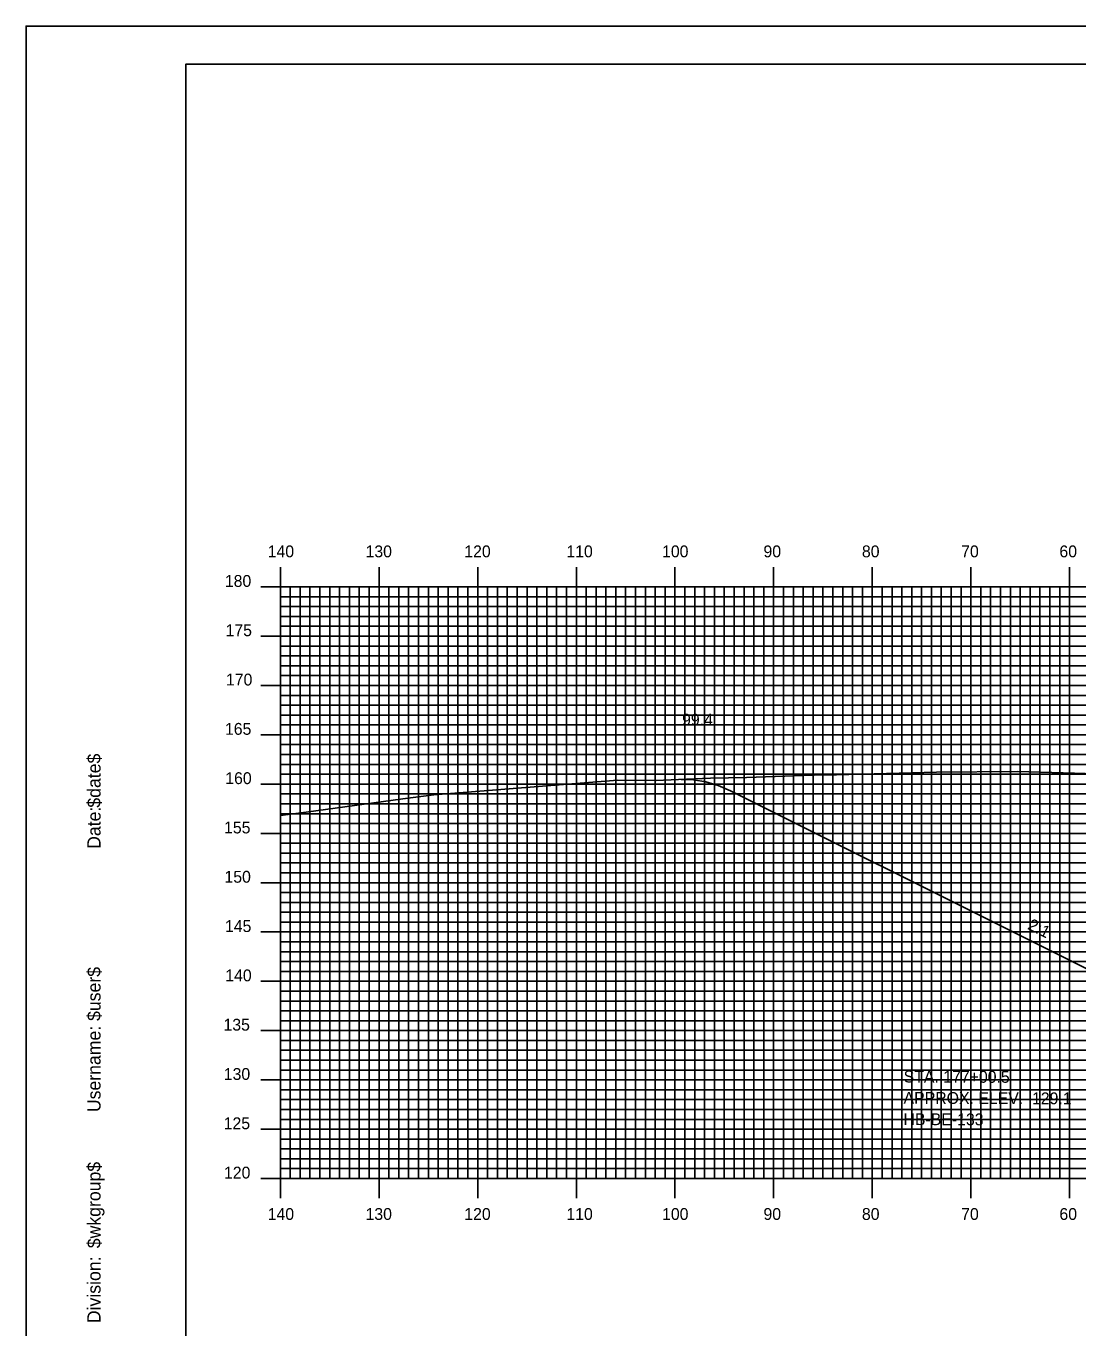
# Model space of a CAD drawing. Extents: x 1784615 to 1784958, y 442591 to 442811.
# Drawn here: x 1784614.7 to 1784721.4, y 442678.5 to 442810.5 of the extents above; entities that cross this region are included whole.
import ezdxf

# ---------------------------------------------------------------- set-up
doc = ezdxf.new("R2010")
doc.units = 0
for name, color, linetype in [('ANNOTATION', 7, 'Continuous'), ('BORDER', 7, 'Continuous'), ('BORING - NO REFUSAL', 7, 'Continuous'), ('D_Roadway_SlopeLines', 7, 'Continuous'), ('D_Text_Standard', 7, 'Continuous'), ('H_V ANNOTATION', 7, 'Continuous'), ('MAJOR', 7, 'Continuous'), ('MINOR', 7, 'Continuous'), ('PLOT BOUNDARY', 7, 'Continuous'), ('S_Roadway_Centerline', 7, 'Continuous')]:
    doc.layers.add(name, color=color, linetype=linetype)

msp = doc.modelspace()

# ---------------------------------------------------------------- linework, layer by layer
at = {"layer": 'BORDER'}
msp.add_lwpolyline([(1784630.91, 442596.67), (1784950.91, 442596.67), (1784950.91, 442806.67), (1784630.91, 442806.67)], close=True, dxfattribs=at)
at = {"layer": 'D_Roadway_SlopeLines'}
msp.add_lwpolyline([(1784746.34, 442702.89), (1784686.14, 442732.99), (1784684.89, 442733.53), (1784683.64, 442733.91), (1784682.39, 442734.11), (1784681.14, 442734.14)], dxfattribs=at)
at = {"layer": 'MAJOR'}
for p, q in [((1784640.51, 442755.67), (1784640.51, 442753.67)), ((1784650.51, 442755.67), (1784650.51, 442753.67)), ((1784660.51, 442755.67), (1784660.51, 442753.67)), ((1784670.51, 442755.67), (1784670.51, 442753.67)), ((1784680.51, 442755.67), (1784680.51, 442753.67)), ((1784690.51, 442755.67), (1784690.51, 442753.67)), ((1784700.51, 442755.67), (1784700.51, 442753.67)), ((1784710.51, 442755.67), (1784710.51, 442753.67)), ((1784720.51, 442755.67), (1784720.51, 442753.67)), ((1784638.51, 442753.67), (1784640.51, 442753.67)), ((1784640.51, 442753.67), (1784920.51, 442753.67)), ((1784640.51, 442693.67), (1784640.51, 442753.67)), ((1784640.51, 442693.67), (1784640.51, 442753.67)), ((1784640.51, 442753.67), (1784920.51, 442753.67)), ((1784650.51, 442693.67), (1784650.51, 442753.67)), ((1784660.51, 442693.67), (1784660.51, 442753.67)), ((1784670.51, 442693.67), (1784670.51, 442753.67)), ((1784680.51, 442693.67), (1784680.51, 442753.67)), ((1784690.51, 442693.67), (1784690.51, 442753.67)), ((1784700.51, 442693.67), (1784700.51, 442753.67)), ((1784710.51, 442693.67), (1784710.51, 442753.67)), ((1784720.51, 442693.67), (1784720.51, 442753.67)), ((1784638.51, 442748.67), (1784640.51, 442748.67)), ((1784640.51, 442748.67), (1784920.51, 442748.67)), ((1784638.51, 442743.67), (1784640.51, 442743.67)), ((1784640.51, 442743.67), (1784920.51, 442743.67)), ((1784638.51, 442738.67), (1784640.51, 442738.67)), ((1784640.51, 442738.67), (1784920.51, 442738.67)), ((1784638.51, 442733.67), (1784640.51, 442733.67)), ((1784640.51, 442733.67), (1784920.51, 442733.67)), ((1784638.51, 442728.67), (1784640.51, 442728.67)), ((1784640.51, 442728.67), (1784920.51, 442728.67)), ((1784638.51, 442723.67), (1784640.51, 442723.67)), ((1784640.51, 442723.67), (1784920.51, 442723.67)), ((1784638.51, 442718.67), (1784640.51, 442718.67)), ((1784640.51, 442718.67), (1784920.51, 442718.67)), ((1784638.51, 442713.67), (1784640.51, 442713.67)), ((1784640.51, 442713.67), (1784920.51, 442713.67)), ((1784638.51, 442708.67), (1784640.51, 442708.67)), ((1784640.51, 442708.67), (1784920.51, 442708.67)), ((1784638.51, 442703.67), (1784640.51, 442703.67)), ((1784640.51, 442703.67), (1784920.51, 442703.67)), ((1784638.51, 442698.67), (1784640.51, 442698.67)), ((1784640.51, 442698.67), (1784920.51, 442698.67)), ((1784638.51, 442693.67), (1784640.51, 442693.67)), ((1784640.51, 442693.67), (1784920.51, 442693.67)), ((1784640.51, 442693.67), (1784920.51, 442693.67)), ((1784640.51, 442691.66), (1784640.51, 442693.67)), ((1784650.51, 442691.66), (1784650.51, 442693.67)), ((1784660.51, 442691.66), (1784660.51, 442693.67)), ((1784670.51, 442691.66), (1784670.51, 442693.67)), ((1784680.51, 442691.66), (1784680.51, 442693.67)), ((1784690.51, 442691.66), (1784690.51, 442693.67)), ((1784700.51, 442691.66), (1784700.51, 442693.67)), ((1784710.51, 442691.66), (1784710.51, 442693.67)), ((1784720.51, 442691.66), (1784720.51, 442693.67))]:
    msp.add_line(p, q, dxfattribs=at)
at = {"layer": 'MINOR'}
for p, q in [((1784641.51, 442693.67), (1784641.51, 442753.67)), ((1784642.51, 442693.67), (1784642.51, 442753.67)), ((1784643.51, 442693.67), (1784643.51, 442753.67)), ((1784644.51, 442693.67), (1784644.51, 442753.67)), ((1784645.51, 442693.67), (1784645.51, 442753.67)), ((1784646.51, 442693.67), (1784646.51, 442753.67)), ((1784647.51, 442693.67), (1784647.51, 442753.67)), ((1784648.51, 442693.67), (1784648.51, 442753.67)), ((1784649.51, 442693.67), (1784649.51, 442753.67)), ((1784651.51, 442693.67), (1784651.51, 442753.67)), ((1784652.51, 442693.67), (1784652.51, 442753.67)), ((1784653.51, 442693.67), (1784653.51, 442753.67)), ((1784654.51, 442693.67), (1784654.51, 442753.67)), ((1784655.51, 442693.67), (1784655.51, 442753.67)), ((1784656.51, 442693.67), (1784656.51, 442753.67)), ((1784657.51, 442693.67), (1784657.51, 442753.67)), ((1784658.51, 442693.67), (1784658.51, 442753.67)), ((1784659.51, 442693.67), (1784659.51, 442753.67)), ((1784661.51, 442693.67), (1784661.51, 442753.67)), ((1784662.51, 442693.67), (1784662.51, 442753.67)), ((1784663.51, 442693.67), (1784663.51, 442753.67)), ((1784664.51, 442693.67), (1784664.51, 442753.67)), ((1784665.51, 442693.67), (1784665.51, 442753.67)), ((1784666.51, 442693.67), (1784666.51, 442753.67)), ((1784667.51, 442693.67), (1784667.51, 442753.67)), ((1784668.51, 442693.67), (1784668.51, 442753.67)), ((1784669.51, 442693.67), (1784669.51, 442753.67)), ((1784671.51, 442693.67), (1784671.51, 442753.67)), ((1784672.51, 442693.67), (1784672.51, 442753.67)), ((1784673.51, 442693.67), (1784673.51, 442753.67)), ((1784674.51, 442693.67), (1784674.51, 442753.67)), ((1784675.51, 442693.67), (1784675.51, 442753.67)), ((1784676.51, 442693.67), (1784676.51, 442753.67)), ((1784677.51, 442693.67), (1784677.51, 442753.67)), ((1784678.51, 442693.67), (1784678.51, 442753.67)), ((1784679.51, 442693.67), (1784679.51, 442753.67)), ((1784681.51, 442693.67), (1784681.51, 442753.67)), ((1784682.51, 442693.67), (1784682.51, 442753.67)), ((1784683.51, 442693.67), (1784683.51, 442753.67)), ((1784684.51, 442693.67), (1784684.51, 442753.67)), ((1784685.51, 442693.67), (1784685.51, 442753.67)), ((1784686.51, 442693.67), (1784686.51, 442753.67)), ((1784687.51, 442693.67), (1784687.51, 442753.67)), ((1784688.51, 442693.67), (1784688.51, 442753.67)), ((1784689.51, 442693.67), (1784689.51, 442753.67)), ((1784691.51, 442693.67), (1784691.51, 442753.67)), ((1784692.51, 442693.67), (1784692.51, 442753.67)), ((1784693.51, 442693.67), (1784693.51, 442753.67)), ((1784694.51, 442693.67), (1784694.51, 442753.67)), ((1784695.51, 442693.67), (1784695.51, 442753.67)), ((1784696.51, 442693.67), (1784696.51, 442753.67)), ((1784697.51, 442693.67), (1784697.51, 442753.67)), ((1784698.51, 442693.67), (1784698.51, 442753.67)), ((1784699.51, 442693.67), (1784699.51, 442753.67)), ((1784701.51, 442693.67), (1784701.51, 442753.67)), ((1784702.51, 442693.67), (1784702.51, 442753.67)), ((1784703.51, 442693.67), (1784703.51, 442753.67)), ((1784704.51, 442693.67), (1784704.51, 442753.67)), ((1784705.51, 442693.67), (1784705.51, 442753.67)), ((1784706.51, 442693.67), (1784706.51, 442753.67)), ((1784707.51, 442693.67), (1784707.51, 442753.67)), ((1784708.51, 442693.67), (1784708.51, 442753.67)), ((1784709.51, 442693.67), (1784709.51, 442753.67)), ((1784711.51, 442693.67), (1784711.51, 442753.67)), ((1784712.51, 442693.67), (1784712.51, 442753.67)), ((1784713.51, 442693.67), (1784713.51, 442753.67)), ((1784714.51, 442693.67), (1784714.51, 442753.67)), ((1784715.51, 442693.67), (1784715.51, 442753.67)), ((1784716.51, 442693.67), (1784716.51, 442753.67)), ((1784717.51, 442693.67), (1784717.51, 442753.67)), ((1784718.51, 442693.67), (1784718.51, 442753.67)), ((1784719.51, 442693.67), (1784719.51, 442753.67)), ((1784640.51, 442752.67), (1784920.51, 442752.67)), ((1784640.51, 442752.67), (1784642.52, 442752.67)), ((1784640.51, 442751.67), (1784920.51, 442751.67)), ((1784640.51, 442751.67), (1784642.52, 442751.67)), ((1784640.51, 442750.67), (1784920.51, 442750.67)), ((1784640.51, 442750.67), (1784642.52, 442750.67)), ((1784640.51, 442749.67), (1784920.51, 442749.67)), ((1784640.51, 442749.67), (1784642.52, 442749.67)), ((1784640.51, 442747.67), (1784920.51, 442747.67)), ((1784640.51, 442747.67), (1784642.52, 442747.67)), ((1784640.51, 442746.67), (1784920.51, 442746.67)), ((1784640.51, 442746.67), (1784642.52, 442746.67)), ((1784640.51, 442745.67), (1784920.51, 442745.67)), ((1784640.51, 442745.67), (1784642.52, 442745.67)), ((1784640.51, 442744.67), (1784920.51, 442744.67)), ((1784640.51, 442744.67), (1784642.52, 442744.67)), ((1784640.51, 442742.67), (1784920.51, 442742.67)), ((1784640.51, 442742.67), (1784642.52, 442742.67)), ((1784640.51, 442741.67), (1784920.51, 442741.67)), ((1784640.51, 442741.67), (1784642.52, 442741.67)), ((1784640.51, 442740.67), (1784920.51, 442740.67)), ((1784640.51, 442740.67), (1784642.52, 442740.67)), ((1784640.51, 442739.67), (1784920.51, 442739.67)), ((1784640.51, 442739.67), (1784642.52, 442739.67)), ((1784640.51, 442737.67), (1784920.51, 442737.67)), ((1784640.51, 442737.67), (1784642.52, 442737.67)), ((1784640.51, 442736.67), (1784920.51, 442736.67)), ((1784640.51, 442736.67), (1784642.52, 442736.67)), ((1784640.51, 442735.67), (1784920.51, 442735.67)), ((1784640.51, 442735.67), (1784642.52, 442735.67)), ((1784640.51, 442734.67), (1784920.51, 442734.67)), ((1784640.51, 442734.67), (1784642.52, 442734.67)), ((1784640.51, 442732.67), (1784920.51, 442732.67)), ((1784640.51, 442732.67), (1784642.52, 442732.67)), ((1784640.51, 442731.67), (1784920.51, 442731.67)), ((1784640.51, 442731.67), (1784642.52, 442731.67)), ((1784640.51, 442730.67), (1784920.51, 442730.67)), ((1784640.51, 442730.67), (1784642.52, 442730.67)), ((1784640.51, 442729.67), (1784920.51, 442729.67)), ((1784640.51, 442729.67), (1784642.52, 442729.67)), ((1784640.51, 442727.67), (1784920.51, 442727.67)), ((1784640.51, 442727.67), (1784642.52, 442727.67)), ((1784640.51, 442726.67), (1784920.51, 442726.67)), ((1784640.51, 442726.67), (1784642.52, 442726.67)), ((1784640.51, 442725.67), (1784920.51, 442725.67)), ((1784640.51, 442725.67), (1784642.52, 442725.67)), ((1784640.51, 442724.67), (1784920.51, 442724.67)), ((1784640.51, 442724.67), (1784642.52, 442724.67)), ((1784640.51, 442722.67), (1784920.51, 442722.67)), ((1784640.51, 442722.67), (1784642.52, 442722.67)), ((1784640.51, 442721.67), (1784920.51, 442721.67)), ((1784640.51, 442721.67), (1784642.52, 442721.67)), ((1784640.51, 442720.67), (1784920.51, 442720.67)), ((1784640.51, 442720.67), (1784642.52, 442720.67)), ((1784640.51, 442719.67), (1784920.51, 442719.67)), ((1784640.51, 442719.67), (1784642.52, 442719.67)), ((1784640.51, 442717.67), (1784920.51, 442717.67)), ((1784640.51, 442717.67), (1784642.52, 442717.67)), ((1784640.51, 442716.67), (1784920.51, 442716.67)), ((1784640.51, 442716.67), (1784642.52, 442716.67)), ((1784640.51, 442715.67), (1784920.51, 442715.67)), ((1784640.51, 442715.67), (1784642.52, 442715.67)), ((1784640.51, 442714.67), (1784920.51, 442714.67)), ((1784640.51, 442714.67), (1784642.52, 442714.67)), ((1784640.51, 442712.67), (1784920.51, 442712.67)), ((1784640.51, 442712.67), (1784642.52, 442712.67)), ((1784640.51, 442711.67), (1784920.51, 442711.67)), ((1784640.51, 442711.67), (1784642.52, 442711.67)), ((1784640.51, 442710.67), (1784920.51, 442710.67)), ((1784640.51, 442710.67), (1784642.52, 442710.67)), ((1784640.51, 442709.67), (1784920.51, 442709.67)), ((1784640.51, 442709.67), (1784642.52, 442709.67)), ((1784640.51, 442707.67), (1784920.51, 442707.67)), ((1784640.51, 442707.67), (1784642.52, 442707.67)), ((1784640.51, 442706.67), (1784920.51, 442706.67)), ((1784640.51, 442706.67), (1784642.52, 442706.67)), ((1784640.51, 442705.67), (1784920.51, 442705.67)), ((1784640.51, 442705.67), (1784642.52, 442705.67)), ((1784640.51, 442704.67), (1784920.51, 442704.67)), ((1784640.51, 442704.67), (1784642.52, 442704.67)), ((1784640.51, 442702.67), (1784920.51, 442702.67)), ((1784640.51, 442702.67), (1784642.52, 442702.67)), ((1784640.51, 442701.67), (1784920.51, 442701.67)), ((1784640.51, 442701.67), (1784642.52, 442701.67)), ((1784640.51, 442700.67), (1784920.51, 442700.67)), ((1784640.51, 442700.67), (1784642.52, 442700.67)), ((1784640.51, 442699.67), (1784920.51, 442699.67)), ((1784640.51, 442699.67), (1784642.52, 442699.67)), ((1784640.51, 442697.67), (1784920.51, 442697.67)), ((1784640.51, 442697.67), (1784642.52, 442697.67)), ((1784640.51, 442696.67), (1784920.51, 442696.67)), ((1784640.51, 442696.67), (1784642.52, 442696.67)), ((1784640.51, 442695.67), (1784920.51, 442695.67)), ((1784640.51, 442695.67), (1784642.52, 442695.67)), ((1784640.51, 442694.67), (1784920.51, 442694.67)), ((1784640.51, 442694.67), (1784642.52, 442694.67))]:
    msp.add_line(p, q, dxfattribs=at)
at = {"layer": 'PLOT BOUNDARY'}
msp.add_lwpolyline([(1784614.73, 442590.55), (1784954.73, 442590.55), (1784954.73, 442810.55), (1784614.73, 442810.55)], close=True, dxfattribs=at)
at = {"layer": 'S_Roadway_Centerline'}
msp.add_lwpolyline([(1784640.51, 442730.48), (1784643.12, 442730.83), (1784652.92, 442732.17), (1784656.05, 442732.57), (1784674.71, 442734.07), (1784678.59, 442734.04), (1784680.88, 442734.13), (1784684.11, 442734.26), (1784687.77, 442734.35), (1784693.57, 442734.55), (1784695.65, 442734.62), (1784696.89, 442734.61), (1784707.03, 442734.89), (1784715.23, 442734.96), (1784721.01, 442734.79), (1784727.48, 442734.59)], dxfattribs=at)

# ---------------------------------------------------------------- texts
at = {"layer": 'ANNOTATION'}
msp.add_text('2:1', height=1.2, rotation=333.4349, dxfattribs=at).set_placement((1784716.17, 442719.01))
at = {"layer": 'BORDER'}
for s, p in [('$date$', (1784622.28, 442731.28)), ('$date$', (1784622.28, 442731.28)), ('Date:', (1784622.28, 442727.1)), ('Date:', (1784622.28, 442727.1)), ('$user$', (1784622.28, 442709.65)), ('$user$', (1784622.28, 442709.65)), ('Username:', (1784622.28, 442700.4)), ('Username:', (1784622.28, 442700.4)), ('$wkgroup$', (1784622.28, 442686.6)), ('$wkgroup$', (1784622.28, 442686.6)), ('Division:', (1784622.28, 442679)), ('Division:', (1784622.28, 442679))]:
    msp.add_text(s, height=1.339, rotation=90, dxfattribs=at).set_placement(p)
at = {"layer": 'BORING - NO REFUSAL'}
for s, p in [('STA. 177+00.5', (1784703.69, 442703.41)), ('APPROX. ELEV.  129.1', (1784703.68, 442701.25)), ('HB-BE-133', (1784703.67, 442699.09))]:
    msp.add_text(s, height=1.2, rotation=359.8142, dxfattribs=at).set_placement(p)
at = {"layer": 'D_Text_Standard'}
msp.add_text("99.4'", height=1.2, dxfattribs=at).set_placement((1784681.23, 442739.6))
at = {"layer": 'H_V ANNOTATION'}
for s, p in [('140', (1784639.22, 442756.67)), ('130', (1784649.14, 442756.67)), ('120', (1784659.15, 442756.67)), ('110', (1784669.5, 442756.67)), ('100', (1784679.2, 442756.67)), ('90', (1784689.48, 442756.67)), ('80', (1784699.46, 442756.67)), ('70', (1784709.52, 442756.67)), ('60', (1784719.48, 442756.67)), ('180', (1784634.88, 442753.67)), ('175', (1784634.95, 442748.67)), ('170', (1784634.99, 442743.67)), ('165', (1784634.89, 442738.67)), ('160', (1784634.92, 442733.67)), ('155', (1784634.8, 442728.67)), ('150', (1784634.84, 442723.67)), ('145', (1784634.89, 442718.67)), ('140', (1784634.92, 442713.67)), ('135', (1784634.74, 442708.67)), ('130', (1784634.77, 442703.67)), ('125', (1784634.76, 442698.67)), ('120', (1784634.79, 442693.67)), ('140', (1784639.22, 442689.47)), ('130', (1784649.14, 442689.47)), ('120', (1784659.15, 442689.47)), ('110', (1784669.5, 442689.47)), ('100', (1784679.2, 442689.47)), ('90', (1784689.48, 442689.47)), ('80', (1784699.46, 442689.47)), ('70', (1784709.52, 442689.47)), ('60', (1784719.48, 442689.47))]:
    msp.add_text(s, height=1.2, dxfattribs=at).set_placement(p)
at = {"layer": 'MAJOR'}
msp.add_text('-', height=0.012, dxfattribs=at).set_placement((1784640.5, 442693.67))

doc.saveas('drawing.dxf')
